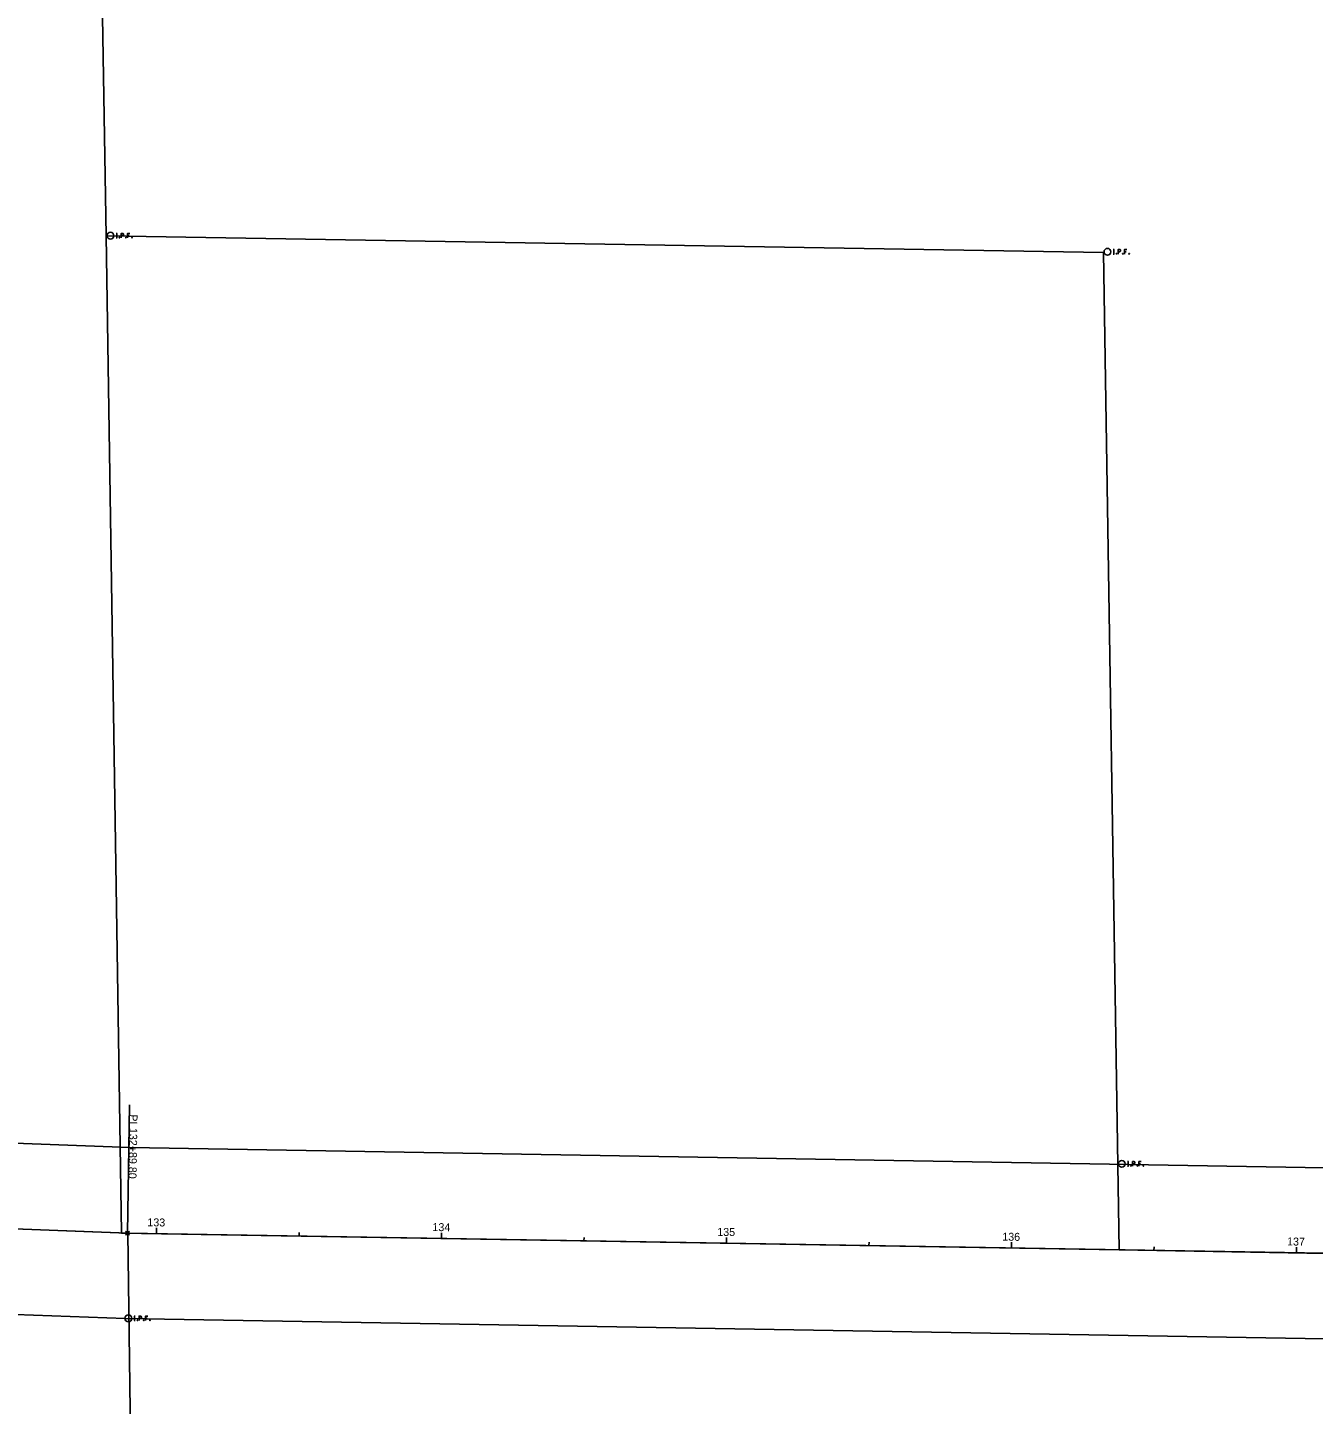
# Model space of a CAD drawing. Extents: x 2003596 to 2006888, y 571866 to 574416.
# Drawn here: x 2005988.6 to 2006439.7, y 572537.1 to 573020.2 of the extents above; entities that cross this region are included whole.
import ezdxf

# ---------------------------------------------------------------- set-up
doc = ezdxf.new("R2010")
doc.units = 0
for name, color, linetype in [('DV_X_Property_Line', 7, 'Continuous'), ('GE_X_Alignment', 7, 'Continuous'), ('GE_X_Alignment_1000_Cardinal_Points', 7, 'Continuous'), ('GE_X_Alignment_1000_Stations', 7, 'Continuous'), ('GE_X_Alignment_100_Cardinal_Points', 7, 'Continuous'), ('GE_X_Alignment_100_Stations', 7, 'Continuous'), ('GE_X_Alignment_500_Cardinal_Points', 7, 'Continuous'), ('GE_X_Alignment_500_Stations', 7, 'Continuous'), ('RW_X_CL', 7, 'Continuous'), ('RW_X_Esmt_SH', 7, 'Continuous'), ('SC_Scratch10', 7, 'Continuous'), ('SC_Scratch9', 7, 'Continuous'), ('SV_X_Mon_Cells_Found', 7, 'Continuous'), ('SV_X_Random_Point', 7, 'Continuous')]:
    doc.layers.add(name, color=color, linetype=linetype)

msp = doc.modelspace()

# ---------------------------------------------------------------- linework, layer by layer
at = {"layer": 'DV_X_Property_Line'}
for p, q in [((2006016.1, 572947.15), (2005993.24, 574409.1)), ((2006366.05, 572941.3), (2006016.1, 572947.15)), ((2006016.1, 572947.15), (2006021.57, 572597.33)), ((2006371.52, 572591.4), (2006366.05, 572941.3)), ((2006033.93, 571867.27), (2006023.71, 572597.25))]:
    msp.add_line(p, q, dxfattribs=at)
at = {"layer": 'GE_X_Alignment'}
for p, q in [((2005031.48, 572635.32), (2006023.62, 572597.25)), ((2006023.62, 572597.25), (2006884.1, 572582.77))]:
    msp.add_line(p, q, dxfattribs=at)
at = {"layer": 'GE_X_Alignment_1000_Cardinal_Points'}
msp.add_line((2006023.62, 572597.25), (2006024.38, 572642.24), dxfattribs=at)
msp.add_circle((2006023.62, 572597.25), 0.6, dxfattribs=at)
at = {"layer": 'GE_X_Alignment_1000_Stations'}
msp.add_line((2006233.79, 572593.71), (2006233.81, 572594.91), dxfattribs=at)
at = {"layer": 'GE_X_Alignment_100_Cardinal_Points'}
msp.add_line((2006023.62, 572597.25), (2006024.38, 572642.24), dxfattribs=at)
msp.add_circle((2006023.62, 572597.25), 0.6, dxfattribs=at)
at = {"layer": 'GE_X_Alignment_100_Stations'}
for p, q in [((2006033.82, 572597.08), (2006033.85, 572599.08)), ((2006083.81, 572596.24), (2006083.83, 572597.44)), ((2006133.81, 572595.4), (2006133.84, 572597.4)), ((2006183.8, 572594.55), (2006183.82, 572595.75)), ((2006233.79, 572593.71), (2006233.82, 572595.71)), ((2006283.78, 572592.87), (2006283.8, 572594.07)), ((2006333.78, 572592.03), (2006333.81, 572594.03)), ((2006383.77, 572591.19), (2006383.79, 572592.39)), ((2006433.76, 572590.35), (2006433.8, 572592.35))]:
    msp.add_line(p, q, dxfattribs=at)
at = {"layer": 'GE_X_Alignment_500_Cardinal_Points'}
msp.add_line((2006023.62, 572597.25), (2006024.38, 572642.24), dxfattribs=at)
msp.add_circle((2006023.62, 572597.25), 0.6, dxfattribs=at)
at = {"layer": 'GE_X_Alignment_500_Stations'}
for p, q in [((2006033.82, 572597.08), (2006033.84, 572598.28)), ((2006133.81, 572595.4), (2006133.83, 572596.6)), ((2006233.79, 572593.71), (2006233.82, 572595.71)), ((2006333.78, 572592.03), (2006333.8, 572593.23)), ((2006433.76, 572590.35), (2006433.78, 572591.55))]:
    msp.add_line(p, q, dxfattribs=at)
at = {"layer": 'RW_X_CL'}
for p, q in [((2006023.62, 572597.25), (2005031.48, 572635.32)), ((2006884.1, 572582.77), (2006023.62, 572597.25))]:
    msp.add_line(p, q, dxfattribs=at)
at = {"layer": 'RW_X_Esmt_SH'}
for p, q in [((2005034.78, 572665.22), (2006024.45, 572627.24)), ((2006024.45, 572627.24), (2006839.11, 572613.53)), ((2005028.18, 572605.42), (2006022.8, 572567.26)), ((2006022.8, 572567.26), (2006839.37, 572553.52))]:
    msp.add_line(p, q, dxfattribs=at)
at = {"layer": 'SC_Scratch10'}
msp.add_line((2006023.71, 572597.25), (2005465.42, 572618.88), dxfattribs=at)
at = {"layer": 'SC_Scratch9'}
for p, q in [((2006371.52, 572591.34), (2006021.57, 572597.19)), ((2006884.1, 572582.77), (2006371.52, 572591.34))]:
    msp.add_line(p, q, dxfattribs=at)
at = {"layer": 'SV_X_Mon_Cells_Found'}
for points in [[(2006019.68, 572947.96), (2006020.03, 572947.96)], [(2006019.68, 572946.36), (2006020.03, 572946.36)], [(2006019.85, 572946.36), (2006019.85, 572947.96)], [(2006020.81, 572946.58), (2006020.87, 572946.58), (2006020.9, 572946.55), (2006020.93, 572946.5), (2006020.93, 572946.44), (2006020.9, 572946.39), (2006020.87, 572946.36), (2006020.81, 572946.36), (2006020.78, 572946.39), (2006020.75, 572946.44), (2006020.75, 572946.5), (2006020.78, 572946.55), (2006020.81, 572946.58)], [(2006021.42, 572946.36), (2006021.42, 572947.96), (2006021.95, 572947.96), (2006022, 572947.95), (2006022.08, 572947.93), (2006022.11, 572947.9), (2006022.15, 572947.88), (2006022.19, 572947.81), (2006022.22, 572947.75), (2006022.25, 572947.65), (2006022.25, 572947.5), (2006022.24, 572947.45), (2006022.21, 572947.37), (2006022.17, 572947.28), (2006022.12, 572947.25), (2006022.09, 572947.22), (2006022.04, 572947.2), (2006021.95, 572947.18), (2006021.42, 572947.18)], [(2006023.06, 572946.58), (2006023.12, 572946.58), (2006023.15, 572946.55), (2006023.18, 572946.5), (2006023.18, 572946.44), (2006023.15, 572946.39), (2006023.12, 572946.36), (2006023.06, 572946.36), (2006023.03, 572946.39), (2006023, 572946.44), (2006023, 572946.5), (2006023.03, 572946.55), (2006023.06, 572946.58)], [(2006024.43, 572947.96), (2006023.67, 572947.96), (2006023.67, 572946.36)], [(2006023.67, 572947.18), (2006024.21, 572947.18)], [(2006025.21, 572946.58), (2006025.27, 572946.58), (2006025.3, 572946.55), (2006025.33, 572946.5), (2006025.33, 572946.44), (2006025.3, 572946.39), (2006025.27, 572946.36), (2006025.21, 572946.36), (2006025.18, 572946.39), (2006025.15, 572946.44), (2006025.15, 572946.5), (2006025.18, 572946.55), (2006025.21, 572946.58)], [(2006369.47, 572942.32), (2006369.83, 572942.32)], [(2006369.47, 572940.72), (2006369.83, 572940.72)], [(2006369.65, 572940.72), (2006369.65, 572942.32)], [(2006370.61, 572940.94), (2006370.66, 572940.94), (2006370.7, 572940.91), (2006370.73, 572940.86), (2006370.73, 572940.8), (2006370.7, 572940.75), (2006370.66, 572940.72), (2006370.61, 572940.72), (2006370.58, 572940.75), (2006370.54, 572940.8), (2006370.54, 572940.86), (2006370.58, 572940.91), (2006370.61, 572940.94)], [(2006371.22, 572940.72), (2006371.22, 572942.32), (2006371.74, 572942.32), (2006371.8, 572942.31), (2006371.88, 572942.29), (2006371.91, 572942.26), (2006371.94, 572942.24), (2006371.99, 572942.17), (2006372.02, 572942.11), (2006372.04, 572942.01), (2006372.04, 572941.86), (2006372.03, 572941.81), (2006372.01, 572941.73), (2006371.96, 572941.64), (2006371.92, 572941.61), (2006371.89, 572941.58), (2006371.83, 572941.56), (2006371.74, 572941.54), (2006371.22, 572941.54)], [(2006372.86, 572940.94), (2006372.91, 572940.94), (2006372.95, 572940.91), (2006372.98, 572940.86), (2006372.98, 572940.8), (2006372.95, 572940.75), (2006372.91, 572940.72), (2006372.86, 572940.72), (2006372.82, 572940.75), (2006372.79, 572940.8), (2006372.79, 572940.86), (2006372.82, 572940.91), (2006372.86, 572940.94)], [(2006374.22, 572942.32), (2006373.46, 572942.32), (2006373.46, 572940.72)], [(2006373.46, 572941.54), (2006374, 572941.54)], [(2006375.01, 572940.94), (2006375.06, 572940.94), (2006375.1, 572940.91), (2006375.13, 572940.86), (2006375.13, 572940.8), (2006375.1, 572940.75), (2006375.06, 572940.72), (2006375.01, 572940.72), (2006374.97, 572940.75), (2006374.94, 572940.8), (2006374.94, 572940.86), (2006374.97, 572940.91), (2006375.01, 572940.94)], [(2006374.5, 572622.36), (2006374.86, 572622.36)], [(2006374.5, 572620.76), (2006374.86, 572620.76)], [(2006374.68, 572620.76), (2006374.68, 572622.36)], [(2006375.64, 572620.97), (2006375.69, 572620.97), (2006375.73, 572620.95), (2006375.76, 572620.9), (2006375.76, 572620.84), (2006375.73, 572620.79), (2006375.69, 572620.76), (2006375.64, 572620.76), (2006375.61, 572620.79), (2006375.57, 572620.84), (2006375.57, 572620.9), (2006375.61, 572620.95), (2006375.64, 572620.97)], [(2006376.25, 572620.76), (2006376.25, 572622.36), (2006376.77, 572622.36), (2006376.83, 572622.35), (2006376.91, 572622.32), (2006376.94, 572622.3), (2006376.97, 572622.27), (2006377.02, 572622.21), (2006377.05, 572622.15), (2006377.07, 572622.05), (2006377.07, 572621.89), (2006377.06, 572621.84), (2006377.04, 572621.77), (2006377, 572621.68), (2006376.95, 572621.64), (2006376.92, 572621.62), (2006376.86, 572621.59), (2006376.77, 572621.58), (2006376.25, 572621.58)], [(2006377.89, 572620.97), (2006377.94, 572620.97), (2006377.98, 572620.95), (2006378.01, 572620.9), (2006378.01, 572620.84), (2006377.98, 572620.79), (2006377.94, 572620.76), (2006377.89, 572620.76), (2006377.86, 572620.79), (2006377.82, 572620.84), (2006377.82, 572620.9), (2006377.86, 572620.95), (2006377.89, 572620.97)], [(2006379.26, 572622.36), (2006378.49, 572622.36), (2006378.49, 572620.76)], [(2006378.49, 572621.58), (2006379.03, 572621.58)], [(2006380.04, 572620.97), (2006380.09, 572620.97), (2006380.13, 572620.95), (2006380.16, 572620.9), (2006380.16, 572620.84), (2006380.13, 572620.79), (2006380.09, 572620.76), (2006380.04, 572620.76), (2006380, 572620.79), (2006379.97, 572620.84), (2006379.97, 572620.9), (2006380, 572620.95), (2006380.04, 572620.97)], [(2006025.97, 572568.15), (2006026.33, 572568.15)], [(2006025.97, 572566.55), (2006026.33, 572566.55)], [(2006026.15, 572566.55), (2006026.15, 572568.15)], [(2006027.11, 572566.76), (2006027.16, 572566.76), (2006027.2, 572566.74), (2006027.23, 572566.69), (2006027.23, 572566.63), (2006027.2, 572566.58), (2006027.16, 572566.55), (2006027.11, 572566.55), (2006027.08, 572566.58), (2006027.04, 572566.63), (2006027.04, 572566.69), (2006027.08, 572566.74), (2006027.11, 572566.76)], [(2006027.72, 572566.55), (2006027.72, 572568.15), (2006028.24, 572568.15), (2006028.3, 572568.14), (2006028.38, 572568.11), (2006028.41, 572568.09), (2006028.44, 572568.06), (2006028.49, 572568), (2006028.52, 572567.94), (2006028.54, 572567.84), (2006028.54, 572567.68), (2006028.53, 572567.63), (2006028.51, 572567.56), (2006028.47, 572567.47), (2006028.42, 572567.43), (2006028.39, 572567.41), (2006028.33, 572567.38), (2006028.24, 572567.37), (2006027.72, 572567.37)], [(2006029.36, 572566.76), (2006029.41, 572566.76), (2006029.45, 572566.74), (2006029.48, 572566.69), (2006029.48, 572566.63), (2006029.45, 572566.58), (2006029.41, 572566.55), (2006029.36, 572566.55), (2006029.32, 572566.58), (2006029.29, 572566.63), (2006029.29, 572566.69), (2006029.32, 572566.74), (2006029.36, 572566.76)], [(2006030.72, 572568.15), (2006029.96, 572568.15), (2006029.96, 572566.55)], [(2006029.96, 572567.37), (2006030.5, 572567.37)], [(2006031.51, 572566.76), (2006031.56, 572566.76), (2006031.6, 572566.74), (2006031.63, 572566.69), (2006031.63, 572566.63), (2006031.6, 572566.58), (2006031.56, 572566.55), (2006031.51, 572566.55), (2006031.47, 572566.58), (2006031.44, 572566.63), (2006031.44, 572566.69), (2006031.47, 572566.74), (2006031.51, 572566.76)]]:
    msp.add_lwpolyline(points, dxfattribs=at)
for centre in [(2006017.66, 572947.16), (2006367.46, 572941.52), (2006372.49, 572621.56), (2006023.96, 572567.35)]:
    msp.add_circle(centre, 1.2, dxfattribs=at)
at = {"layer": 'SV_X_Random_Point'}
for p, q in [((2006022.96, 572596.58), (2006024.29, 572597.92)), ((2006022.96, 572597.92), (2006024.29, 572596.58))]:
    msp.add_line(p, q, dxfattribs=at)

# ---------------------------------------------------------------- texts
at = {"layer": 'GE_X_Alignment_1000_Cardinal_Points'}
for s, p in [('PI', (2006024.37, 572638.95)), ('132+89.80', (2006024.29, 572634.17))]:
    msp.add_text(s, height=2.8, rotation=269.0359, dxfattribs=at).set_placement(p)
at = {"layer": 'GE_X_Alignment_100_Cardinal_Points'}
for s, p in [('PI', (2006024.37, 572638.95)), ('132+89.80', (2006024.29, 572634.17))]:
    msp.add_text(s, height=2.8, rotation=269.0359, dxfattribs=at).set_placement(p)
at = {"layer": 'GE_X_Alignment_100_Stations'}
for s, p in [('133', (2006030.6, 572599.68)), ('134', (2006130.61, 572598)), ('135', (2006230.54, 572596.32)), ('136', (2006330.54, 572594.63)), ('137', (2006430.47, 572592.95))]:
    msp.add_text(s, height=2.8, rotation=359.0359, dxfattribs=at).set_placement(p)
at = {"layer": 'GE_X_Alignment_500_Cardinal_Points'}
for s, p in [('PI', (2006024.37, 572638.95)), ('132+89.80', (2006024.29, 572634.17))]:
    msp.add_text(s, height=2.8, rotation=269.0359, dxfattribs=at).set_placement(p)
at = {"layer": 'GE_X_Alignment_500_Stations'}
msp.add_text('135', height=2.8, rotation=359.0359, dxfattribs=at).set_placement((2006230.54, 572596.32))

doc.saveas('drawing.dxf')
